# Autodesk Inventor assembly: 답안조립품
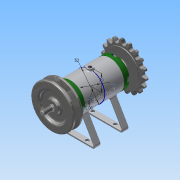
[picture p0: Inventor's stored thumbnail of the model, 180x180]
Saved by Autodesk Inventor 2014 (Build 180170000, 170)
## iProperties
Created: 2016-03
Part Number: 답안조립품
Document SubType Name: Assembly
Designer: net
Author: net
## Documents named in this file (13)
- C:\Users\net\Desktop\460307V1005\답안조립품.iam
- C:\Users\net\Desktop\460307V1005\본체.ipt
- C:\Users\net\Desktop\460307V1005\볼트 M4 x 12.ipt
- C:\Users\net\Desktop\460307V1005\축.ipt
- C:\Users\net\Desktop\460307V1005\커버.ipt
- C:\Users\net\Desktop\460307V1005\베어링 15 x 32 x 9.ipt
- C:\Users\net\Desktop\460307V1005\오일 실 15 25 7.ipt
- C:\Users\net\Desktop\460307V1005\너트 M 8.ipt
- C:\Users\net\Desktop\460307V1005\스프로킷.ipt
- C:\Users\net\Desktop\460307V1005\스프링와셔 8.ipt
- C:\Users\net\Desktop\460307V1005\와셔 8x17.ipt
- C:\Users\net\Desktop\460307V1005\키 3 x 3 x 12.ipt
- C:\Users\net\Desktop\460307V1005\V벨트풀리.ipt
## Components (8 placed, 3 different names)
1. ISO 4762 M4 x 12:5
2. KS B 2023 6002 - 15 x 32 x 9:1
3. KS B 2023 6002 - 15 x 32 x 9:2
4. V벨트풀리:1
5. ISO 4762 M4 x 12:1
6. ISO 4762 M4 x 12:2
7. ISO 4762 M4 x 12:3
8. ISO 4762 M4 x 12:4
